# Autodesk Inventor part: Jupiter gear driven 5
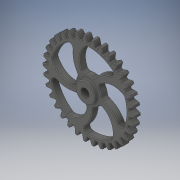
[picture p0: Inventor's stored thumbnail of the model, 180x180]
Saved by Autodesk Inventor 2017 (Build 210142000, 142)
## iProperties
Created: 2016-05
Part Number: Jupiter gear driven 5
Material: Generic
Document SubType Name: Modeling
Designer: Stan
Density: 1 g/cm^3
Appearance: Gray
Author: Stan
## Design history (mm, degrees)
sketch "Sketch1"
  geometry: A1 r 20.854 centre (26.488, -28.842) between (8.197, -38.858) and (11.164, -42.986); A2 r 20.854 centre (26.488, -28.842) between (8.197, -38.858) and (11.164, -42.986); A3 r 20.854 centre (-14.28, -36.463) between (5.118, -44.116) and (6.394, -39.195); A4 r 20.854 centre (-14.28, -36.463) between (5.118, -44.116) and (6.394, -39.195); A5 r 20.854 centre (31.336, -23.484) between (15.198, -36.69) and (18.873, -40.203); A6 r 20.854 centre (31.336, -23.484) between (15.198, -36.69) and (18.873, -40.203); A7 r 20.854 centre (-7.337, -38.466) between (13.137, -42.425) and (13.487, -37.353); A8 r 20.854 centre (-7.337, -38.466) between (13.137, -42.425) and (13.487, -37.353); A9 r 20.854 centre (35.118, -17.326) between (21.681, -33.273) and (25.939, -36.05); A10 r 20.854 centre (35.118, -17.326) between (21.681, -33.273) and (25.939, -36.05); A11 r 20.854 centre (-0.144, -39.159) between (20.709, -39.288) and (20.121, -34.239); A12 r 20.854 centre (-0.144, -39.159) between (20.709, -39.288) and (20.121, -34.239); A13 r 20.854 centre (37.704, -10.578) between (27.425, -28.723) and (32.121, -30.67); A14 r 20.854 centre (37.704, -10.578) between (27.425, -28.723) and (32.121, -30.67); A15 r 20.854 centre (7.054, -38.519) between (27.576, -34.814) and (26.07, -29.959); A16 r 20.854 centre (7.054, -38.519) between (27.576, -34.814) and (26.07, -29.959); A17 r 20.854 centre (39.005, -3.47) between (32.236, -23.194) and (37.21, -24.246); A18 r 20.854 centre (39.005, -3.47) between (32.236, -23.194) and (37.21, -24.246); A19 r 20.854 centre (14.012, -36.567) between (33.503, -29.154) and (31.131, -24.658); A20 r 20.854 centre (14.012, -36.567) between (33.503, -29.154) and (31.131, -24.658); A21 r 20.854 centre (38.979, 3.757) between (35.949, -16.876) and (41.031, -16.996); A22 r 20.854 centre (38.979, 3.757) between (35.949, -16.876) and (41.031, -16.996); A23 r 20.854 centre (20.492, -33.37) between (38.29, -22.502) and (35.131, -18.518); A24 r 20.854 centre (20.492, -33.37) between (38.29, -22.502) and (35.131, -18.518); A25 r 20.854 centre (37.625, 10.855) between (38.438, -9.983) and (43.456, -9.167); A26 r 20.854 centre (37.625, 10.855) between (38.438, -9.983) and (43.456, -9.167); A27 r 20.854 centre (26.275, -29.036) between (41.773, -15.083) and (37.936, -11.747); A28 r 20.854 centre (26.275, -29.036) between (41.773, -15.083) and (37.936, -11.747); A29 r 20.854 centre (34.99, 17.584) between (39.618, -2.75) and (44.4, -1.026); A30 r 20.854 centre (34.99, 17.584) between (39.618, -2.75) and (44.4, -1.026); A31 r 20.854 centre (31.163, -23.714) between (43.833, -7.15) and (39.449, -4.577); A32 r 20.854 centre (31.163, -23.714) between (43.833, -7.15) and (39.449, -4.577); A33 r 20.854 centre (31.163, 23.714) between (39.449, 4.577) and (43.833, 7.15); A34 r 20.854 centre (31.163, 23.714) between (39.449, 4.577) and (43.833, 7.15); A35 r 20.854 centre (34.99, -17.584) between (44.4, 1.026) and (39.618, 2.75); A36 r 20.854 centre (34.99, -17.584) between (44.4, 1.026) and (39.618, 2.75); A37 r 20.854 centre (26.275, 29.036) between (37.936, 11.747) and (41.773, 15.083); A38 r 20.854 centre (26.275, 29.036) between (37.936, 11.747) and (41.773, 15.083); A39 r 20.854 centre (37.625, -10.855) between (43.456, 9.167) and (38.438, 9.983); A40 r 20.854 centre (37.625, -10.855) between (43.456, 9.167) and (38.438, 9.983); A41 r 20.854 centre (20.492, 33.37) between (35.131, 18.518) and (38.29, 22.502); A42 r 20.854 centre (20.492, 33.37) between (35.131, 18.518) and (38.29, 22.502); A43 r 20.854 centre (38.979, -3.757) between (41.031, 16.996) and (35.949, 16.876); A44 r 20.854 centre (38.979, -3.757) between (41.031, 16.996) and (35.949, 16.876); A45 r 20.854 centre (14.012, 36.567) between (31.131, 24.658) and (33.503, 29.154); A46 r 20.854 centre (14.012, 36.567) between (31.131, 24.658) and (33.503, 29.154); A47 r 20.854 centre (39.005, 3.47) between (37.21, 24.246) and (32.236, 23.194); A48 r 20.854 centre (39.005, 3.47) between (37.21, 24.246) and (32.236, 23.194); A49 r 20.854 centre (7.054, 38.519) between (26.07, 29.959) and (27.576, 34.814); A50 r 20.854 centre (7.054, 38.519) between (26.07, 29.959) and (27.576, 34.814); A51 r 20.854 centre (37.704, 10.578) between (32.121, 30.67) and (27.425, 28.723); A52 r 20.854 centre (37.704, 10.578) between (32.121, 30.67) and (27.425, 28.723); A53 r 20.854 centre (-0.144, 39.159) between (20.121, 34.239) and (20.709, 39.288); A54 r 20.854 centre (-0.144, 39.159) between (20.121, 34.239) and (20.709, 39.288); A55 r 20.854 centre (35.118, 17.326) between (25.939, 36.05) and (21.681, 33.273); A56 r 20.854 centre (35.118, 17.326) between (25.939, 36.05) and (21.681, 33.273); A57 r 20.854 centre (-7.337, 38.466) between (13.487, 37.353) and (13.137, 42.425); A58 r 20.854 centre (-7.337, 38.466) between (13.487, 37.353) and (13.137, 42.425); A59 r 20.854 centre (31.336, 23.484) between (18.873, 40.203) and (15.198, 36.69); A60 r 20.854 centre (31.336, 23.484) between (18.873, 40.203) and (15.198, 36.69); A61 r 20.854 centre (-14.28, 36.463) between (6.394, 39.195) and (5.118, 44.116); A62 r 20.854 centre (-14.28, 36.463) between (6.394, 39.195) and (5.118, 44.116); A63 r 20.854 centre (26.488, 28.842) between (11.164, 42.986) and (8.197, 38.858); A64 r 20.854 centre (26.488, 28.842) between (11.164, 42.986) and (8.197, 38.858)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; 1 further point
  constraints: 544 point on circle, 272 centre point, 8 horizontal alignment, 8 vertical alignment, 800 other
  dimensions: "d0" = 0 dimension on point (0, 0); "d1" = 0 dimension on point (0, 0)
extrude "Extrusion1" new body sketch "Sketch1" distance "d2" = 6.35; taper "d3" = 0 deg
sketch "Sketch2"
  geometry: C1 r 3.969 at (0, 0); 1 further point
  constraints: 1 centre point, 1 coincident
  dimensions: "d4" = 7.9375 diameter of C1
extrude "Extrusion2" cut sketch "Sketch2" distance "d5" = 6.35; taper "d6" = 0 deg
sketch "Sketch3"
  geometry: A1 r 36.513 centre (0, 0) between (-8.745, -35.45) and (22.733, -28.572); A2 r 36.513 centre (0, 0) between (31.012, -19.272) and (34.199, 12.791); A3 r 36.513 centre (0, 0) between (27.912, 23.539) and (-1.597, 36.478); A4 r 36.513 centre (0, 0) between (-13.762, 33.82) and (-35.253, 9.506); A5 r 36.513 centre (0, 0) between (-36.417, -2.638) and (-19.934, -30.591); A6 r 26.136 centre (10.543, 24.21) between (-13.762, 33.82) and (-9.912, 7.941); A7 r 19.198 centre (10.719, 21.75) between (-1.597, 36.478) and (-5.485, 11.455); A8 r 26.136 centre (-19.767, 17.508) between (-36.417, -2.638) and (-10.615, -6.973); A9 r 19.198 centre (-17.272, 16.231) between (-35.253, 9.506) and (-12.479, -2.359); A10 r 26.136 centre (-22.246, -13.071) between (-8.745, -35.45) and (3.872, -12.095); A11 r 19.198 centre (-20.774, -11.411) between (-19.934, -30.591) and (-1.613, -12.597); A12 r 26.136 centre (5.701, -25.783) between (31.012, -19.272) and (12.686, -0.598); A13 r 19.198 centre (4.113, -23.897) between (22.733, -28.572) and (11.17, -6.043); A14 r 26.136 centre (26.283, -2.546) between (27.912, 23.539) and (4.489, 11.88); A15 r 19.198 centre (23.998, -3.473) between (34.199, 12.791) and (9.199, 8.756); A16 r 12.7 centre (0, 0) between (-9.912, 7.941) and (-12.479, -2.359); A17 r 12.7 centre (0, 0) between (-10.615, -6.973) and (-1.613, -12.597); A18 r 12.7 centre (0, 0) between (3.872, -12.095) and (11.17, -6.043); A19 r 12.7 centre (0, 0) between (12.686, -0.598) and (9.199, 8.756); A20 r 12.7 centre (0, 0) between (4.489, 11.88) and (-5.485, 11.455); 2 further points
  constraints: 40 point on circle, 20 centre point
  dimensions: "d7" = 0 distance of point (0, 0) A1.centre; "d8" = 0 distance of A1.centre point (0, 0); "d9" = 36.5125 radius of A3; "d10" = 36.5125 radius of A2; "d11" = 36.5125 radius of A1; "d12" = 36.5125 radius of A5; "d13" = 36.5125 radius of A4; "d14" = 0 distance of point (0, 0) point (0, 0); "d15" = 0 distance of point (0, 0) point (0, 0); "d16" = 12.7 radius of A17; "d17" = 12.7 radius of A18; "d18" = 12.7 radius of A19; "d19" = 12.7 radius of A20; "d20" = 12.7 radius of A16
extrude "Extrusion3" cut sketch "Sketch3" distance "d21" = 6.35; taper "d22" = 0 deg
fillet "Fillet1" dims "d23" = 3.175
sketch "Sketch4"
  geometry: C1 r 9.525 at (0, 0); C2 r 3.969 at (0, 0); 1 further point
  constraints: 2 centre point, 2 coincident
  dimensions: "d24" = 19.05 diameter of C1
extrude "Extrusion4" join sketch "Sketch4" distance "d25" = 3.175; taper "d26" = 0 deg
fillet "Fillet2" dims "d27" = 0.79375
fillet "Fillet3" dims "d28" = 0.79375
fillet "Fillet4" dims "d29" = 0.79375
fillet "Fillet5" dims "d30" = 0.79375
fillet "Fillet6" dims "d31" = 0.79375
fillet "Fillet7" dims "d32" = 0.79375
body "Solid1"
